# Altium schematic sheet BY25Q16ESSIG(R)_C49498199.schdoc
size 127 x 101 mm
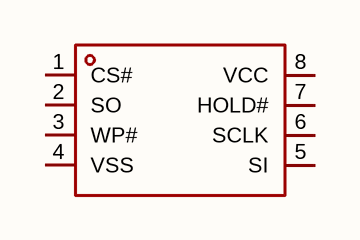
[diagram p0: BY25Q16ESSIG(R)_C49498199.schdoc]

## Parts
U?  by25q16essig(r)_c49498199  [SOP-8_L5.3-W5.3-P1.27-LS7.9-BL]  (value not drawn)

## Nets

Not connected (* = marked no-connect by the designer): U? 1(CS#) 2(SO) 3(WP#) 4(VSS) 5(SI) 6(SCLK) 7(HOLD#) 8(VCC)

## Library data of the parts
U? = by25q16essig(r)_c49498199: 接口类型:SPI;存储容量:16Mbit;时钟频率(fc):108MHz;; Manufacturer: BOYAMICRO(博雅); AddInBom: yes; ModelId: 72eaeed142424588879d6a198b07ab72; ModelTransform: 207.67675,311.023,0,0,0,0,0,0,0; Interface: SPI; Memory Size: 16Mbit; Clock Frequency: 108MHz; Voltage - Supply: 2.7V~3.6V; Standby Supply Current: 2.5uA; Program / Erase Cycles: 100000次; Page Programming Time (Tpp): 160us; Block Erase Time(tBE): 200ms; Data Retention - TDR (Year): 20年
